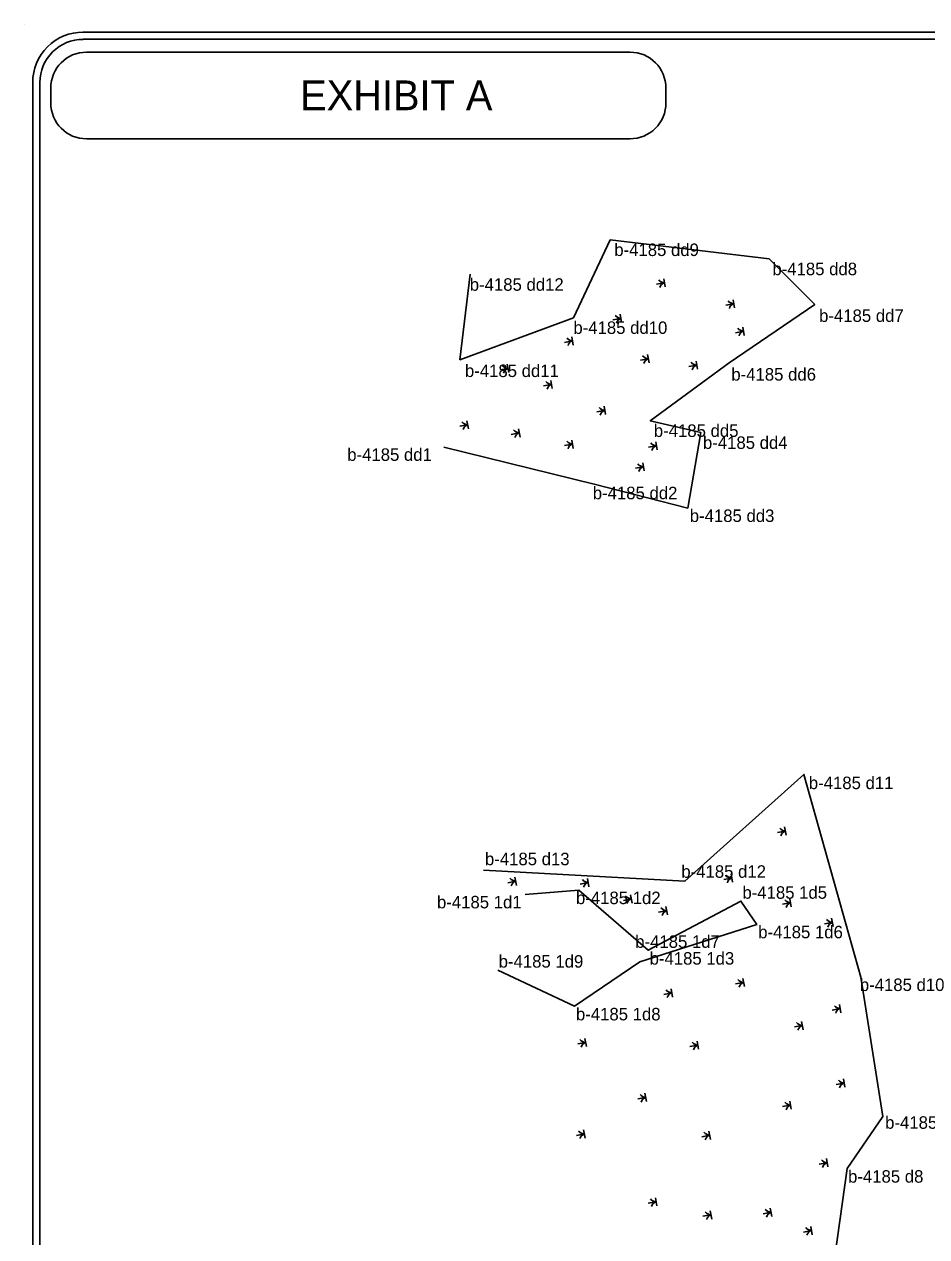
# Model space of a CAD drawing. Extents: x 2598976 to 2600165, y 728604 to 730243.
# Drawn here: x 2598976 to 2599517, y 729516 to 730243 of the extents above; entities that cross this region are included whole.
import ezdxf

# ---------------------------------------------------------------- set-up
doc = ezdxf.new("R2010")
doc.units = 0
for name, color, linetype in [('Old_Level_24', 7, 'Continuous'), ('Old_Level_3', 7, 'Continuous'), ('Old_Level_57', 7, 'Continuous'), ('Old_Level_63', 7, 'Continuous')]:
    doc.layers.add(name, color=color, linetype=linetype)

msp = doc.modelspace()

# ---------------------------------------------------------------- linework, layer by layer
at = {"layer": 'Old_Level_3'}
for p, q in [((2599326.96, 730113.64), (2599326.96, 730113.64)), ((2599422.41, 730102.19), (2599422.41, 730102.19)), ((2599242.98, 730093.08), (2599242.98, 730093.08)), ((2599449.63, 730074.98), (2599449.63, 730074.98)), ((2599304.97, 730066.93), (2599304.97, 730066.93)), ((2599236.86, 730041.82), (2599236.86, 730041.82)), ((2599398.28, 730039.99), (2599398.28, 730039.99)), ((2599350.98, 730005.17), (2599350.98, 730005.17)), ((2599381.37, 729998.14), (2599381.37, 729998.14)), ((2599227.31, 729989.33), (2599227.31, 729989.33)), ((2599317.45, 729967.17), (2599317.45, 729967.17)), ((2599373.48, 729952.8), (2599373.48, 729952.8)), ((2599443.13, 729793.12), (2599443.13, 729793.12)), ((2599251, 729735.76), (2599251, 729735.76)), ((2599308.23, 729723.63), (2599308.23, 729723.63)), ((2599371.81, 729729.07), (2599371.81, 729729.07)), ((2599275.97, 729721.14), (2599275.97, 729721.14)), ((2599405.4, 729717.13), (2599405.4, 729717.13)), ((2599414.92, 729703.17), (2599414.92, 729703.17)), ((2599349.67, 729687.7), (2599349.67, 729687.7)), ((2599344.76, 729680.8), (2599344.76, 729680.8)), ((2599259.59, 729675.65), (2599259.59, 729675.65)), ((2599477.33, 729671.46), (2599477.33, 729671.46)), ((2599305.69, 729654.07), (2599305.69, 729654.07)), ((2599469.1, 729556.89), (2599469.1, 729556.89))]:
    msp.add_line(p, q, dxfattribs=at)
at = {"layer": 'Old_Level_57'}
for p, q in [((2599359.55, 730087.89), (2599354.76, 730087.03)), ((2599359.99, 730085.43), (2599359.11, 730090.35)), ((2599401.14, 730075.31), (2599396.35, 730074.45)), ((2599401.58, 730072.85), (2599400.71, 730077.77)), ((2599333.43, 730066.6), (2599328.64, 730065.74)), ((2599333.87, 730064.14), (2599332.99, 730069.06)), ((2599406.95, 730058.86), (2599402.16, 730058)), ((2599407.39, 730056.39), (2599406.51, 730061.32)), ((2599304.41, 730053.05), (2599299.62, 730052.2)), ((2599304.85, 730050.59), (2599303.97, 730055.51)), ((2599349.88, 730042.4), (2599345.08, 730041.55)), ((2599350.31, 730039.94), (2599349.44, 730044.86)), ((2599265.72, 730036.6), (2599260.93, 730035.74)), ((2599266.16, 730034.14), (2599265.28, 730039.06)), ((2599378.9, 730038.53), (2599374.1, 730037.68)), ((2599379.33, 730036.07), (2599378.46, 730040.99)), ((2599292.27, 730024.46), (2599291.4, 730029.38)), ((2599291.84, 730026.92), (2599287.04, 730026.07)), ((2599324.2, 730008.97), (2599323.32, 730013.9)), ((2599323.76, 730011.44), (2599318.97, 730010.58)), ((2599241.53, 730002.73), (2599236.74, 730001.87)), ((2599241.97, 730000.26), (2599241.1, 730005.19)), ((2599272.93, 729995.43), (2599272.05, 730000.35)), ((2599272.49, 729997.89), (2599267.7, 729997.03)), ((2599304.85, 729988.65), (2599303.97, 729993.57)), ((2599355.15, 729987.68), (2599354.27, 729992.61)), ((2599304.41, 729991.11), (2599299.62, 729990.26)), ((2599354.71, 729990.15), (2599349.92, 729989.29)), ((2599346.97, 729977.57), (2599342.18, 729976.71)), ((2599347.41, 729975.1), (2599346.53, 729980.03)), ((2599432.04, 729759.17), (2599427.25, 729758.32)), ((2599432.48, 729756.71), (2599431.6, 729761.63)), ((2599270.76, 729726.58), (2599269.89, 729731.51)), ((2599314.17, 729725.79), (2599313.29, 729730.72)), ((2599399.95, 729730.99), (2599395.16, 729730.13)), ((2599400.39, 729728.52), (2599399.51, 729733.45)), ((2599270.32, 729729.05), (2599265.53, 729728.19)), ((2599313.73, 729728.26), (2599308.94, 729727.4)), ((2599339.69, 729718.46), (2599334.9, 729717.61)), ((2599340.13, 729716), (2599339.25, 729720.92)), ((2599435.17, 729716.11), (2599430.38, 729715.26)), ((2599435.61, 729713.65), (2599434.73, 729718.57)), ((2599360.82, 729711.41), (2599356.03, 729710.56)), ((2599361.26, 729708.95), (2599360.38, 729713.87)), ((2599460.22, 729704.37), (2599455.42, 729703.51)), ((2599460.65, 729701.9), (2599459.78, 729706.83)), ((2599364.39, 729659.62), (2599363.51, 729664.55)), ((2599407, 729668.35), (2599402.21, 729667.5)), ((2599407.43, 729665.89), (2599406.56, 729670.81)), ((2599363.95, 729662.09), (2599359.16, 729661.23)), ((2599464.91, 729652.69), (2599460.12, 729651.84)), ((2599465.35, 729650.23), (2599464.47, 729655.15)), ((2599442.21, 729642.51), (2599437.42, 729641.66)), ((2599442.65, 729640.05), (2599441.78, 729644.97)), ((2599312.3, 729632.33), (2599307.51, 729631.48)), ((2599312.74, 729629.87), (2599311.86, 729634.79)), ((2599379.6, 729630.77), (2599374.81, 729629.91)), ((2599380.04, 729628.31), (2599379.17, 729633.23)), ((2599467.26, 729608.06), (2599462.47, 729607.21)), ((2599467.7, 729605.6), (2599466.82, 729610.52)), ((2599348.3, 729599.45), (2599343.51, 729598.59)), ((2599348.74, 729596.99), (2599347.86, 729601.91)), ((2599435.17, 729594.75), (2599430.38, 729593.9)), ((2599435.61, 729592.29), (2599434.73, 729597.21)), ((2599311.51, 729577.53), (2599306.72, 729576.67)), ((2599311.95, 729575.06), (2599311.08, 729579.99)), ((2599387.09, 729574.28), (2599386.21, 729579.2)), ((2599386.65, 729576.74), (2599381.86, 729575.89)), ((2599457.52, 729557.84), (2599456.65, 729562.76)), ((2599457.08, 729560.3), (2599452.29, 729559.45)), ((2599354.56, 729536.81), (2599349.77, 729535.96)), ((2599355, 729534.35), (2599354.12, 729539.27)), ((2599387.43, 729528.98), (2599382.64, 729528.13)), ((2599387.87, 729526.52), (2599386.99, 729531.44)), ((2599423.43, 729530.55), (2599418.64, 729529.69)), ((2599423.87, 729528.09), (2599422.99, 729533.01)), ((2599447.69, 729519.59), (2599442.9, 729518.73)), ((2599448.13, 729517.12), (2599447.25, 729522.05))]:
    msp.add_line(p, q, dxfattribs=at)
for points in [[(2599227.31, 729989.33), (2599317.45, 729967.17), (2599373.48, 729952.8), (2599381.37, 729998.14), (2599350.98, 730005.17), (2599398.28, 730039.99), (2599449.63, 730074.98), (2599422.41, 730102.19), (2599326.96, 730113.64), (2599304.97, 730066.93), (2599236.86, 730041.82), (2599242.98, 730093.08)], [(2599471.85, 729295.85), (2599449.61, 729349.02), (2599415.76, 729320.71), (2599399.91, 729342.76), (2599446.79, 729391.93), (2599460.2, 729494.04), (2599469.1, 729556.89), (2599490.39, 729587.95), (2599477.33, 729671.46), (2599443.13, 729793.12), (2599371.81, 729729.07), (2599251, 729735.76)], [(2599275.97, 729721.14), (2599308.23, 729723.63), (2599349.67, 729687.7), (2599405.4, 729717.13), (2599414.92, 729703.17), (2599344.76, 729680.8), (2599305.69, 729654.07), (2599259.59, 729675.65)]]:
    msp.add_lwpolyline(points, dxfattribs=at)
for centre, radius, start, end in [((2599360.02, 730093.02), 5.15, 220.90031, 264.24799), ((2599360.6, 730084.13), 3.87, 105.65345, 165.99432), ((2599401.61, 730080.44), 5.15, 220.90031, 264.24799), ((2599402.19, 730071.55), 3.87, 105.65345, 165.99432), ((2599333.9, 730071.73), 5.15, 220.90031, 264.24799), ((2599334.48, 730062.84), 3.87, 105.65345, 165.99432), ((2599407.41, 730063.99), 5.15, 220.90031, 264.24799), ((2599408, 730055.1), 3.87, 105.65345, 165.99432), ((2599304.88, 730058.18), 5.15, 220.90031, 264.24799), ((2599305.46, 730049.3), 3.87, 105.65345, 165.99432), ((2599350.34, 730047.54), 5.15, 220.90031, 264.24799), ((2599350.92, 730038.65), 3.87, 105.65345, 165.99432), ((2599266.18, 730041.73), 5.15, 220.90031, 264.24799), ((2599266.77, 730032.84), 3.87, 105.65345, 165.99432), ((2599379.36, 730043.67), 5.15, 220.90031, 264.24799), ((2599379.94, 730034.78), 3.87, 105.65345, 165.99432), ((2599292.3, 730032.05), 5.15, 220.90031, 264.24799), ((2599292.88, 730023.17), 3.87, 105.65345, 165.99432), ((2599324.22, 730016.57), 5.15, 220.90031, 264.24799), ((2599324.81, 730007.68), 3.87, 105.65345, 165.99432), ((2599242, 730007.86), 5.15, 220.90031, 264.24799), ((2599242.58, 729998.97), 3.87, 105.65345, 165.99432), ((2599272.96, 730003.02), 5.15, 220.90031, 264.24799), ((2599273.54, 729994.14), 3.87, 105.65345, 165.99432), ((2599304.88, 729996.25), 5.15, 220.90031, 264.24799), ((2599355.18, 729995.28), 5.15, 220.90031, 264.24799), ((2599305.46, 729987.36), 3.87, 105.65345, 165.99432), ((2599355.76, 729986.39), 3.87, 105.65345, 165.99432), ((2599347.44, 729982.7), 5.15, 220.90031, 264.24799), ((2599348.02, 729973.81), 3.87, 105.65345, 165.99432), ((2599432.51, 729764.31), 5.15, 220.90031, 264.24799), ((2599433.09, 729755.42), 3.87, 105.65345, 165.99432), ((2599270.79, 729734.18), 5.15, 220.90031, 264.24799), ((2599314.2, 729733.39), 5.15, 220.90031, 264.24799), ((2599400.42, 729736.12), 5.15, 220.90031, 264.24799), ((2599401, 729727.23), 3.87, 105.65345, 165.99432), ((2599271.37, 729725.29), 3.87, 105.65345, 165.99432), ((2599314.78, 729724.5), 3.87, 105.65345, 165.99432), ((2599340.16, 729723.59), 5.15, 220.90031, 264.24799), ((2599340.74, 729714.71), 3.87, 105.65345, 165.99432), ((2599435.64, 729721.24), 5.15, 220.90031, 264.24799), ((2599436.22, 729712.36), 3.87, 105.65345, 165.99432), ((2599361.29, 729716.55), 5.15, 220.90031, 264.24799), ((2599361.87, 729707.66), 3.87, 105.65345, 165.99432), ((2599460.68, 729709.5), 5.15, 220.90031, 264.24799), ((2599461.26, 729700.61), 3.87, 105.65345, 165.99432), ((2599407.46, 729673.48), 5.15, 220.90031, 264.24799), ((2599408.04, 729664.6), 3.87, 105.65345, 165.99432), ((2599364.42, 729667.22), 5.15, 220.90031, 264.24799), ((2599365, 729658.33), 3.87, 105.65345, 165.99432), ((2599465.38, 729657.82), 5.15, 220.90031, 264.24799), ((2599465.96, 729648.94), 3.87, 105.65345, 165.99432), ((2599442.68, 729647.65), 5.15, 220.90031, 264.24799), ((2599443.26, 729638.76), 3.87, 105.65345, 165.99432), ((2599312.76, 729637.47), 5.15, 220.90031, 264.24799), ((2599313.35, 729628.58), 3.87, 105.65345, 165.99432), ((2599380.07, 729635.9), 5.15, 220.90031, 264.24799), ((2599380.65, 729627.01), 3.87, 105.65345, 165.99432), ((2599467.73, 729613.19), 5.15, 220.90031, 264.24799), ((2599468.31, 729604.31), 3.87, 105.65345, 165.99432), ((2599348.77, 729604.58), 5.15, 220.90031, 264.24799), ((2599349.35, 729595.7), 3.87, 105.65345, 165.99432), ((2599435.64, 729599.88), 5.15, 220.90031, 264.24799), ((2599436.22, 729591), 3.87, 105.65345, 165.99432), ((2599311.98, 729582.66), 5.15, 220.90031, 264.24799), ((2599312.56, 729573.77), 3.87, 105.65345, 165.99432), ((2599387.11, 729581.88), 5.15, 220.90031, 264.24799), ((2599387.7, 729572.99), 3.87, 105.65345, 165.99432), ((2599457.55, 729565.43), 5.15, 220.90031, 264.24799), ((2599458.13, 729556.55), 3.87, 105.65345, 165.99432), ((2599355.03, 729541.95), 5.15, 220.90031, 264.24799), ((2599355.61, 729533.06), 3.87, 105.65345, 165.99432), ((2599387.9, 729534.12), 5.15, 220.90031, 264.24799), ((2599388.48, 729525.23), 3.87, 105.65345, 165.99432), ((2599423.9, 729535.68), 5.15, 220.90031, 264.24799), ((2599424.48, 729526.79), 3.87, 105.65345, 165.99432), ((2599448.16, 729524.72), 5.15, 220.90031, 264.24799), ((2599448.74, 729515.83), 3.87, 105.65345, 165.99432)]:
    msp.add_arc(centre, radius, start, end, dxfattribs=at)
at = {"layer": 'Old_Level_63'}
for p, q in [((2598975.65, 730242.95), (2598975.65, 730242.95)), ((2599010.7, 730238.21), (2599994, 730238.21)), ((2599010.7, 730238.21), (2599994, 730238.21)), ((2599010.7, 730238.21), (2599994, 730238.21)), ((2599011, 730233.91), (2599994, 730233.91)), ((2599011, 730233.91), (2599994, 730233.91)), ((2599011, 730233.91), (2599994, 730233.91)), ((2599013.03, 730226.21), (2599338.9, 730226.21)), ((2598980.71, 728675.66), (2598980.71, 730208.07)), ((2598980.71, 728675.66), (2598980.71, 730208.07)), ((2598980.71, 728675.66), (2598980.71, 730208.07)), ((2598985.01, 728674.53), (2598985.01, 730208.54)), ((2598985.01, 728674.53), (2598985.01, 730208.54)), ((2598985.01, 728674.53), (2598985.01, 730208.54)), ((2598991.52, 730204.7), (2598991.52, 730195.75)), ((2599360.4, 730204.7), (2599360.4, 730195.77)), ((2599013.03, 730174.24), (2599338.9, 730174.24))]:
    msp.add_line(p, q, dxfattribs=at)
for centre, major_axis, ratio, start_param, end_param in [((2599010.85, 730208.07), (-30.14, 0), 0.999993, 4.706828, 6.283185), ((2599010.85, 730208.07), (-30.14, 0), 0.999993, 4.706828, 6.283185), ((2599010.85, 730208.07), (-30.14, 0), 0.999993, 4.706828, 6.283185), ((2599010.85, 730208.07), (-25.83, 0), 0.999998, 4.706828, 6.283185), ((2599010.85, 730208.07), (-25.83, 0), 0.999998, 4.706828, 6.283185), ((2599010.85, 730208.07), (-25.83, 0), 0.999998, 4.706828, 6.283185), ((2599013.03, 730204.7), (0, -21.51), 0.999998, 3.141593, 4.712389), ((2599338.9, 730204.7), (0, 21.51), 0.999998, 4.712389, 6.283185), ((2599013.03, 730195.75), (0, -21.51), 0.999998, 4.712389, 6.283185), ((2599338.9, 730195.77), (0, 21.53), 0.999998, 3.141591, 4.712389)]:
    msp.add_ellipse(centre, major_axis=major_axis, ratio=ratio, start_param=start_param, end_param=end_param, dxfattribs=at)

# ---------------------------------------------------------------- texts
at = {"layer": 'Old_Level_24'}
for s, p in [('b-4185 dd9', (2599329.45, 730103.97)), ('b-4185 dd8', (2599424.26, 730092.47)), ('b-4185 dd12', (2599242.79, 730083.14)), ('b-4185 dd7', (2599452.26, 730064.46)), ('b-4185 dd10', (2599304.93, 730057.27)), ('b-4185 dd11', (2599239.89, 730031.41)), ('b-4185 dd6', (2599399.64, 730029.26)), ('b-4185 dd5', (2599353.17, 729995.49)), ('b-4185 dd4', (2599382.61, 729988.31)), ('b-4185 dd1', (2599169.32, 729981.13)), ('b-4185 dd2', (2599316.55, 729958.14)), ('b-4185 dd3', (2599374.71, 729944.49)), ('b-4185 d11', (2599446.1, 729784.29)), ('b-4185 d13', (2599251.89, 729738.67)), ('b-4185 d12', (2599369.66, 729731.13)), ('b-4185 1d2', (2599306.47, 729715.33)), ('b-4185 1d5', (2599406.28, 729718.56)), ('b-4185 1d1', (2599223.14, 729712.81)), ('b-4185 1d6', (2599415.76, 729694.85)), ('b-4185 1d7', (2599342.01, 729689.11)), ('b-4185 1d3', (2599350.63, 729679.05)), ('b-4185 1d9', (2599260.12, 729677.25)), ('b-4185 d10', (2599476.68, 729663.24)), ('b-4185 1d8', (2599306.46, 729645.64)), ('b-4185 d9', (2599491.86, 729580.63)), ('b-4185 d8', (2599469.63, 729548.31))]:
    msp.add_text(s, height=7.5, dxfattribs=at).set_placement(p)
at = {"layer": 'Old_Level_63'}
msp.add_text('EXHIBIT A', height=17.831, dxfattribs=at).set_placement((2599141.09, 730191.42))

doc.saveas('drawing.dxf')
